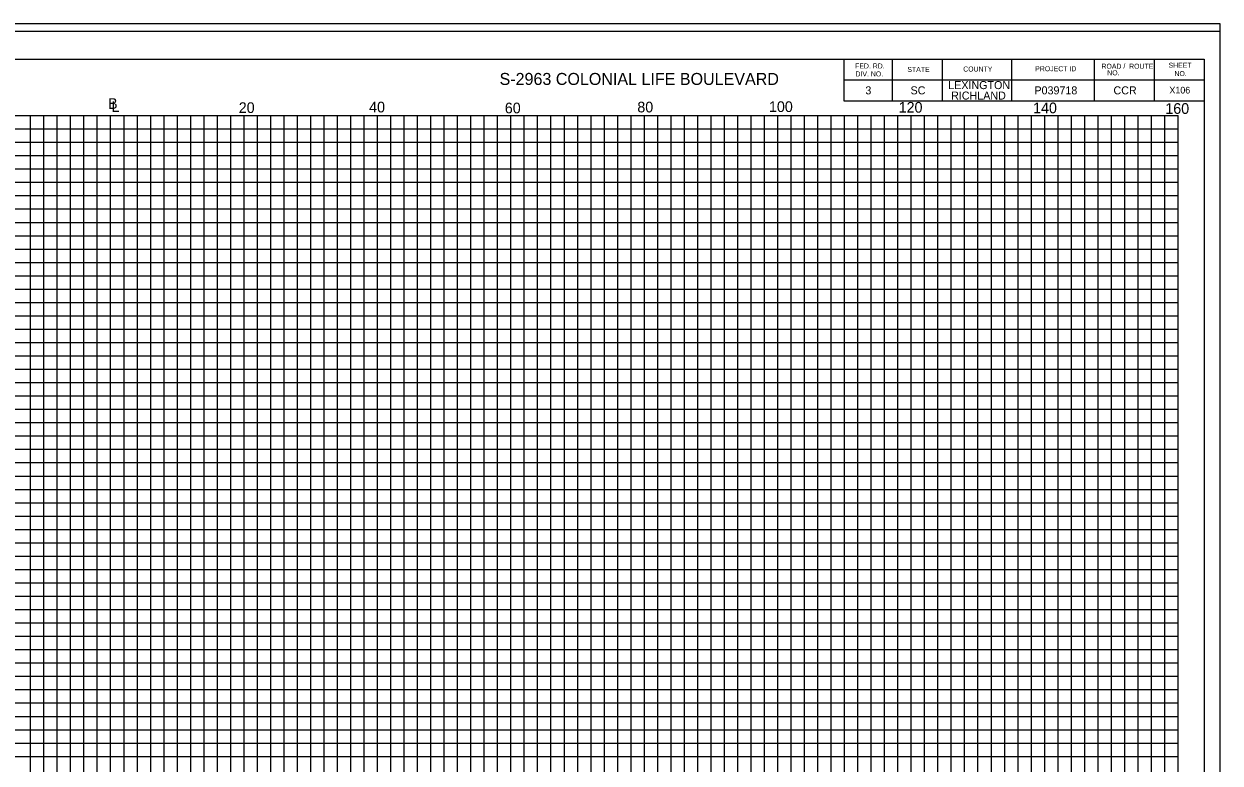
# Model space of a CAD drawing. Extents: x 967 to 1326, y 964 to 1744.
# Drawn here: x 1147 to 1326.3, y 1633 to 1743.7 of the extents above; entities that cross this region are included whole.
import ezdxf

# ---------------------------------------------------------------- set-up
doc = ezdxf.new("R2010")
doc.units = 0
for name, color, linetype in [('Default', 7, 'Continuous'), ('RD_PD_PaveShd', 7, 'Continuous'), ('RD_XS_CurbBase', 7, 'Continuous'), ('RD_XS_TX_Elev_PR', 7, 'Continuous'), ('RD_XS_TX_MkPT', 7, 'Continuous'), ('RD_XS_TX_Slope', 7, 'Continuous'), ('RD_XS_TX_TOC', 7, 'Continuous')]:
    doc.layers.add(name, color=color, linetype=linetype)

msp = doc.modelspace()

# ---------------------------------------------------------------- linework, layer by layer
at = {"layer": 'RD_PD_PaveShd'}
for p, q in [((996.11, 1738.46), (1323.89, 1738.46)), ((1269.89, 1738.46), (1269.89, 1732.21)), ((1277.14, 1738.46), (1277.14, 1732.21)), ((1284.64, 1738.46), (1284.64, 1732.21)), ((1295, 1738.46), (1295, 1732.21)), ((1307.43, 1738.46), (1307.43, 1732.21)), ((1316.39, 1738.46), (1316.39, 1732.21)), ((1323.89, 1738.46), (1323.89, 1528.98)), ((1269.89, 1735.33), (1323.89, 1735.33)), ((1269.89, 1732.21), (1323.89, 1732.21))]:
    msp.add_line(p, q, dxfattribs=at)
at = {"layer": 'RD_XS_CurbBase'}
msp.add_lwpolyline([(967.41, 1523.72), (1326.28, 1523.72), (1326.28, 1743.72), (967.41, 1743.72)], close=True, dxfattribs=at)
at = {"layer": 'RD_XS_TX_Elev_PR'}
for p, q in [((1000, 1730), (1320, 1730)), ((1150, 1560), (1150, 1730)), ((1160, 1560), (1160, 1730)), ((1170, 1560), (1170, 1730)), ((1180, 1560), (1180, 1730)), ((1190, 1560), (1190, 1730)), ((1200, 1560), (1200, 1730)), ((1210, 1560), (1210, 1730)), ((1220, 1560), (1220, 1730)), ((1230, 1560), (1230, 1730)), ((1240, 1560), (1240, 1730)), ((1250, 1560), (1250, 1730)), ((1260, 1560), (1260, 1730)), ((1270, 1560), (1270, 1730)), ((1280, 1560), (1280, 1730)), ((1290, 1560), (1290, 1730)), ((1300, 1560), (1300, 1730)), ((1310, 1560), (1310, 1730)), ((1320, 1560), (1320, 1730)), ((1000, 1720), (1320, 1720)), ((1000, 1710), (1320, 1710)), ((1000, 1700), (1320, 1700)), ((1000, 1690), (1320, 1690)), ((1000, 1680), (1320, 1680)), ((1000, 1670), (1320, 1670)), ((1000, 1660), (1320, 1660)), ((1000, 1650), (1320, 1650)), ((1000, 1640), (1320, 1640))]:
    msp.add_line(p, q, dxfattribs=at)
at = {"layer": 'RD_XS_TX_Slope'}
for p, q in [((1148, 1560), (1148, 1730)), ((1152, 1560), (1152, 1730)), ((1154, 1560), (1154, 1730)), ((1156, 1560), (1156, 1730)), ((1158, 1560), (1158, 1730)), ((1162, 1560), (1162, 1730)), ((1164, 1560), (1164, 1730)), ((1166, 1560), (1166, 1730)), ((1168, 1560), (1168, 1730)), ((1172, 1560), (1172, 1730)), ((1174, 1560), (1174, 1730)), ((1176, 1560), (1176, 1730)), ((1178, 1560), (1178, 1730)), ((1182, 1560), (1182, 1730)), ((1184, 1560), (1184, 1730)), ((1186, 1560), (1186, 1730)), ((1188, 1560), (1188, 1730)), ((1192, 1560), (1192, 1730)), ((1194, 1560), (1194, 1730)), ((1196, 1560), (1196, 1730)), ((1198, 1560), (1198, 1730)), ((1202, 1560), (1202, 1730)), ((1204, 1560), (1204, 1730)), ((1206, 1560), (1206, 1730)), ((1208, 1560), (1208, 1730)), ((1212, 1560), (1212, 1730)), ((1214, 1560), (1214, 1730)), ((1216, 1560), (1216, 1730)), ((1218, 1560), (1218, 1730)), ((1222, 1560), (1222, 1730)), ((1224, 1560), (1224, 1730)), ((1226, 1560), (1226, 1730)), ((1228, 1560), (1228, 1730)), ((1232, 1560), (1232, 1730)), ((1234, 1560), (1234, 1730)), ((1236, 1560), (1236, 1730)), ((1238, 1560), (1238, 1730)), ((1242, 1560), (1242, 1730)), ((1244, 1560), (1244, 1730)), ((1246, 1560), (1246, 1730)), ((1248, 1560), (1248, 1730)), ((1252, 1560), (1252, 1730)), ((1254, 1560), (1254, 1730)), ((1256, 1560), (1256, 1730)), ((1258, 1560), (1258, 1730)), ((1262, 1560), (1262, 1730)), ((1264, 1560), (1264, 1730)), ((1266, 1560), (1266, 1730)), ((1268, 1560), (1268, 1730)), ((1272, 1560), (1272, 1730)), ((1274, 1560), (1274, 1730)), ((1276, 1560), (1276, 1730)), ((1278, 1560), (1278, 1730)), ((1282, 1560), (1282, 1730)), ((1284, 1560), (1284, 1730)), ((1286, 1560), (1286, 1730)), ((1288, 1560), (1288, 1730)), ((1292, 1560), (1292, 1730)), ((1294, 1560), (1294, 1730)), ((1296, 1560), (1296, 1730)), ((1298, 1560), (1298, 1730)), ((1302, 1560), (1302, 1730)), ((1304, 1560), (1304, 1730)), ((1306, 1560), (1306, 1730)), ((1308, 1560), (1308, 1730)), ((1312, 1560), (1312, 1730)), ((1314, 1560), (1314, 1730)), ((1316, 1560), (1316, 1730)), ((1318, 1560), (1318, 1730)), ((1000, 1728), (1320, 1728)), ((1000, 1726), (1320, 1726)), ((1000, 1724), (1320, 1724)), ((1000, 1722), (1320, 1722)), ((1000, 1718), (1320, 1718)), ((1000, 1716), (1320, 1716)), ((1000, 1714), (1320, 1714)), ((1000, 1712), (1320, 1712)), ((1000, 1708), (1320, 1708)), ((1000, 1706), (1320, 1706)), ((1000, 1704), (1320, 1704)), ((1000, 1702), (1320, 1702)), ((1000, 1698), (1320, 1698)), ((1000, 1696), (1320, 1696)), ((1000, 1694), (1320, 1694)), ((1000, 1692), (1320, 1692)), ((1000, 1688), (1320, 1688)), ((1000, 1686), (1320, 1686)), ((1000, 1684), (1320, 1684)), ((1000, 1682), (1320, 1682)), ((1000, 1678), (1320, 1678)), ((1000, 1676), (1320, 1676)), ((1000, 1674), (1320, 1674)), ((1000, 1672), (1320, 1672)), ((1000, 1668), (1320, 1668)), ((1000, 1666), (1320, 1666)), ((1000, 1664), (1320, 1664)), ((1000, 1662), (1320, 1662)), ((1000, 1658), (1320, 1658)), ((1000, 1656), (1320, 1656)), ((1000, 1654), (1320, 1654)), ((1000, 1652), (1320, 1652)), ((1000, 1648), (1320, 1648)), ((1000, 1646), (1320, 1646)), ((1000, 1644), (1320, 1644)), ((1000, 1642), (1320, 1642)), ((1000, 1638), (1320, 1638)), ((1000, 1636), (1320, 1636)), ((1000, 1634), (1320, 1634))]:
    msp.add_line(p, q, dxfattribs=at)
at = {"layer": 'RD_XS_TX_TOC'}
for points in [[(967.41, 1523.72), (1326.28, 1523.72), (1326.28, 1743.72), (967.41, 1743.72)], [(988.52, 1524.84), (1326.28, 1524.84), (1326.28, 1742.6), (988.52, 1742.6)]]:
    msp.add_lwpolyline(points, close=True, dxfattribs=at)

# ---------------------------------------------------------------- texts
at = {"layer": 'Default'}
msp.add_text('X106', height=1, dxfattribs=at).set_placement((1318.69, 1733.3))
at = {"layer": 'RD_XS_TX_MkPT'}
for s, height, p in [('FED. RD.', 0.75, (1271.58, 1737.05)), ('STATE', 0.75, (1279.41, 1736.53)), ('COUNTY', 0.75, (1287.78, 1736.59)), ('PROJECT ID', 0.75, (1298.58, 1736.63)), ('ROAD /  ROUTE', 0.75, (1308.51, 1737.01)), ('SHEET', 0.75, (1318.56, 1737.16)), ('DIV. NO.', 0.75, (1271.64, 1735.86)), ('   NO.', 0.75, (1308.51, 1736.03)), ('NO.', 0.75, (1319.45, 1735.91)), ('3', 1.2, (1273.12, 1733.17)), ('SC', 1.2, (1279.89, 1733.17)), ('LEXINGTON', 1.2, (1285.54, 1733.96)), ('P039718', 1.2, (1298.46, 1733.17)), ('CCR', 1.2, (1310.31, 1733.17)), ('B', 1.6, (1159.61, 1730.99)), ('L', 1.6, (1160.12, 1730.54)), ('20', 1.6, (1179.2, 1730.38)), ('40', 1.6, (1198.74, 1730.47)), ('60', 1.6, (1219.08, 1730.33)), ('80', 1.6, (1238.94, 1730.47)), ('100', 1.6, (1258.67, 1730.53)), ('120', 1.6, (1278.11, 1730.43)), ('RICHLAND', 1.2, (1285.97, 1732.39)), ('140', 1.6, (1298.26, 1730.34)), ('160', 1.6, (1318.08, 1730.25))]:
    msp.add_text(s, height=height, dxfattribs=at).set_placement(p)
msp.add_text('S-2963 COLONIAL LIFE BOULEVARD', height=1.8, rotation=0, dxfattribs=at).set_placement((1218.29, 1734.58))

doc.saveas('drawing.dxf')
